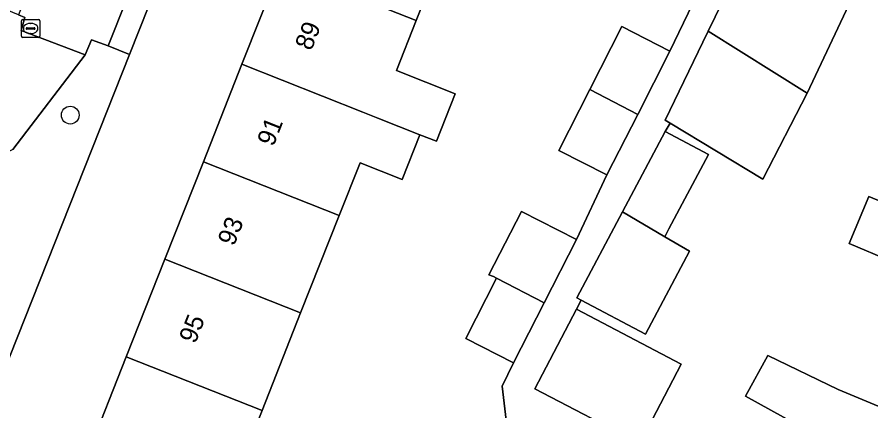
# Model space of a CAD drawing. Extents: x 160349 to 161355, y 381727 to 382854.
# Drawn here: x 160655.2 to 160702.07, y 382076.97 to 382098.58 of the extents above; entities that cross this region are included whole.
import ezdxf

# ---------------------------------------------------------------- set-up
doc = ezdxf.new("R2010")
doc.units = 0
for name, color, linetype in [('IMGEO_Boom', 7, 'Continuous'), ('IMGEO_Erf', 7, 'Continuous'), ('IMGEO_Pand', 7, 'Continuous'), ('IMGEO_Pand_nummerreeks', 7, 'Continuous'), ('IMGEO_Rioolput', 7, 'Continuous'), ('IMGEO_Voetpad_open', 7, 'Continuous'), ('IMGEO_Woonerf_open', 7, 'Continuous')]:
    doc.layers.add(name, color=color, linetype=linetype)

msp = doc.modelspace()

# ---------------------------------------------------------------- linework, layer by layer
at = {"layer": 'IMGEO_Boom'}
msp.add_circle((160658.122, 382093.2), 0.489, dxfattribs=at)
at = {"layer": 'IMGEO_Erf'}
msp.add_lwpolyline([(160669.66, 382101.331), (160671.777, 382106.678), (160673.894, 382112.022), (160676.01, 382117.368), (160678.127, 382122.713), (160680.243, 382128.058), (160682.36, 382133.403), (160684.476, 382138.748), (160686.593, 382144.093), (160688.754, 382149.551), (160683.199, 382151.736), (160672.819, 382125.35), (160661.371, 382096.521), (160642.897, 382049.998), (160648.453, 382047.774), (160650.611, 382053.225), (160652.728, 382058.571), (160654.845, 382063.916), (160656.961, 382069.26), (160659.078, 382074.606), (160661.194, 382079.95), (160663.311, 382085.296), (160665.428, 382090.642), (160667.544, 382095.987)], close=True, dxfattribs=at)
for points in [[(160704.153, 382106.281), (160701.477, 382100.582), (160698.578, 382094.409), (160698.573, 382094.398), (160696.131, 382089.694), (160691.048, 382092.76), (160690.773, 382092.304), (160693.15, 382091.042), (160690.98, 382086.953), (160690.754, 382086.527), (160692.107, 382085.735), (160689.691, 382081.183), (160686.167, 382083.054), (160685.905, 382082.561), (160691.661, 382079.533), (160689.391, 382075.184)], [(160679.231, 382103.728), (160677.114, 382098.382), (160676.031, 382095.647), (160679.253, 382094.371), (160678.22, 382091.762), (160677.313, 382092.121), (160676.343, 382089.67), (160674.027, 382090.586), (160672.881, 382087.692), (160670.765, 382082.347), (160668.648, 382077.001), (160666.532, 382071.656)], [(160682.125, 382075.845), (160681.832, 382078.34), (160682.447, 382079.604), (160679.827, 382080.941), (160681.518, 382084.253), (160681.347, 382084.342), (160681.106, 382084.438), (160682.884, 382087.921), (160685.906, 382086.379), (160687.584, 382089.917), (160684.947, 382091.26), (160686.648, 382094.6), (160688.406, 382098.053), (160691.043, 382096.71), (160692.783, 382100.37)], [(160703.134, 382085.209), (160700.882, 382086.149), (160701.962, 382088.736), (160704.214, 382087.796)], [(160699.198, 382075.578), (160695.196, 382077.779), (160696.423, 382080.009), (160700.271, 382078.147), (160705.011, 382076.169)]]:
    msp.add_lwpolyline(points, dxfattribs=at)
at = {"layer": 'IMGEO_Pand'}
for points in [[(160677.114, 382098.382), (160679.231, 382103.728), (160671.777, 382106.678), (160669.66, 382101.331)], [(160693.141, 382097.801), (160698.573, 382094.398), (160698.578, 382094.409), (160701.477, 382100.582), (160695.79, 382103.252)], [(160677.114, 382098.382), (160669.66, 382101.331), (160667.544, 382095.987), (160674.184, 382093.359), (160674.998, 382093.037), (160677.313, 382092.121), (160678.22, 382091.762), (160679.253, 382094.371), (160676.031, 382095.647)], [(160691.043, 382096.71), (160688.406, 382098.053), (160686.648, 382094.6), (160689.275, 382093.237)], [(160698.573, 382094.398), (160693.141, 382097.801), (160693.107, 382097.731), (160690.776, 382092.924), (160691.048, 382092.76), (160696.131, 382089.694)], [(160677.313, 382092.121), (160674.998, 382093.037), (160674.184, 382093.359), (160667.544, 382095.987), (160665.428, 382090.642), (160672.881, 382087.692), (160674.027, 382090.586), (160676.343, 382089.67)], [(160689.275, 382093.237), (160686.648, 382094.6), (160684.947, 382091.26), (160687.584, 382089.917)], [(160693.15, 382091.042), (160690.773, 382092.304), (160688.43, 382087.889), (160690.754, 382086.527), (160690.98, 382086.953)], [(160663.311, 382085.296), (160670.765, 382082.347), (160672.881, 382087.692), (160665.428, 382090.642)], [(160710.019, 382088.329), (160708.968, 382085.811), (160704.214, 382087.796), (160701.962, 382088.736), (160700.882, 382086.149), (160703.134, 382085.209), (160715.659, 382079.98), (160717.79, 382085.085)], [(160685.906, 382086.379), (160682.884, 382087.921), (160681.106, 382084.438), (160681.347, 382084.342), (160681.518, 382084.253), (160684.129, 382082.899)], [(160692.107, 382085.735), (160690.754, 382086.527), (160688.43, 382087.889), (160685.93, 382083.18), (160686.167, 382083.054), (160689.691, 382081.183)], [(160661.194, 382079.95), (160668.648, 382077.001), (160670.765, 382082.347), (160663.311, 382085.296)], [(160684.129, 382082.899), (160681.518, 382084.253), (160679.827, 382080.941), (160682.447, 382079.604)], [(160685.905, 382082.561), (160683.626, 382078.193), (160689.391, 382075.184), (160691.661, 382079.533)], [(160661.194, 382079.95), (160659.078, 382074.606), (160666.532, 382071.656), (160668.648, 382077.001)], [(160700.271, 382078.147), (160696.423, 382080.009), (160695.196, 382077.779), (160699.198, 382075.578), (160711.651, 382070.378), (160713.624, 382075.104), (160705.911, 382078.324), (160705.011, 382076.169)]]:
    msp.add_lwpolyline(points, close=True, dxfattribs=at)
at = {"layer": 'IMGEO_Rioolput'}
for p, q in [((160655.446, 382097.524), (160655.446, 382098.376)), ((160655.521, 382098.45), (160656.373, 382098.45)), ((160655.934, 382098.23), (160655.959, 382098.23)), ((160656.447, 382098.376), (160656.447, 382097.524)), ((160655.705, 382097.944), (160655.705, 382097.956)), ((160656.143, 382097.907), (160655.745, 382097.907)), ((160655.748, 382097.993), (160656.146, 382097.993)), ((160655.957, 382097.67), (160655.932, 382097.67)), ((160656.189, 382097.956), (160656.189, 382097.944)), ((160656.373, 382097.45), (160655.521, 382097.45))]:
    msp.add_line(p, q, dxfattribs=at)
for points in [[(160655.446, 382097.524), (160655.446, 382098.376)], [(160655.521, 382098.45), (160656.373, 382098.45)], [(160656.447, 382098.376), (160656.447, 382097.524)], [(160656.373, 382097.45), (160655.521, 382097.45)]]:
    msp.add_lwpolyline(points, dxfattribs=at)
for centre, radius, start, end in [((160655.523, 382098.374), 0.0765, 91.552, 178.448), ((160655.523, 382098.374), 0.0765, 91.552, 178.448), ((160656.371, 382098.374), 0.0765, 1.552, 88.448), ((160656.371, 382098.374), 0.0765, 1.552, 88.448), ((160655.745, 382097.953), 0.0403, 85.8775, 175.7526), ((160655.742, 382097.943), 0.0366, 178.938, 274.7102), ((160656.146, 382097.95), 0.043, 264.8664, 352.4533), ((160656.15, 382097.955), 0.0386, 1.7309, 96.639), ((160655.523, 382097.526), 0.0765, 181.552, 268.448), ((160655.523, 382097.526), 0.0765, 181.552, 268.448), ((160656.371, 382097.526), 0.0765, 271.552, 358.448), ((160656.371, 382097.526), 0.0765, 271.552, 358.448)]:
    msp.add_arc(centre, radius, start, end, dxfattribs=at)
for centre, major_axis, ratio, start_param, end_param in [((160655.933, 382097.95), (-0.387, 0.002), 0.722429, 4.712389, 7.853982), ((160655.958, 382097.95), (-0.39, 0.002), 0.717154, 1.570796, 4.712389)]:
    msp.add_ellipse(centre, major_axis=major_axis, ratio=ratio, start_param=start_param, end_param=end_param, dxfattribs=at)
at = {"layer": 'IMGEO_Voetpad_open'}
for points in [[(160674.662, 382139.353), (160671.062, 382130.085), (160669.801, 382126.839), (160668.154, 382122.601), (160667.897, 382121.939), (160668.937, 382121.552), (160667.248, 382117.228), (160664.699, 382110.704), (160665.519, 382110.365), (160660.198, 382097.004), (160661.371, 382096.521), (160672.819, 382125.35), (160683.199, 382151.736)], [(160704.977, 382067.37), (160701.97, 382068.631), (160696.328, 382071.375), (160689.391, 382075.184), (160683.626, 382078.193), (160685.905, 382082.561), (160686.167, 382083.054), (160685.93, 382083.18), (160688.43, 382087.889), (160690.773, 382092.304), (160691.048, 382092.76), (160690.776, 382092.924), (160693.107, 382097.731), (160693.141, 382097.801), (160695.79, 382103.252), (160698.655, 382109.15), (160701.506, 382115.018), (160701.766, 382114.909), (160706.387, 382123.75)], [(160703.159, 382121.024), (160701.44, 382117.39), (160699.598, 382113.899), (160697.818, 382110.526), (160696.952, 382108.872), (160696.016, 382107.084), (160694.346, 382103.616), (160692.783, 382100.37), (160691.043, 382096.71), (160689.275, 382093.237), (160687.584, 382089.917), (160685.906, 382086.379), (160684.129, 382082.899), (160682.447, 382079.604), (160681.832, 382078.34), (160682.125, 382075.845)], [(160654.96, 382091.32), (160658.94, 382096.501), (160655.419, 382097.832), (160655.627, 382098.562), (160655.285, 382098.702), (160651.466, 382100.264)], [(160661.371, 382096.521), (160660.198, 382097.004), (160659.288, 382097.322), (160658.94, 382096.501), (160654.96, 382091.32), (160654.517, 382091.09), (160654.042, 382089.9), (160653.879, 382089.553), (160653.718, 382089.205)], [(160629.825, 382022.664), (160634.111, 382021.11), (160632.646, 382023.106), (160641.875, 382046.842), (160641.985, 382047.125), (160642.897, 382049.998), (160661.371, 382096.521)]]:
    msp.add_lwpolyline(points, dxfattribs=at)
at = {"layer": 'IMGEO_Woonerf_open'}
msp.add_lwpolyline([(160665.519, 382110.365), (160664.699, 382110.704), (160664.643, 382110.561), (160660.563, 382112.113), (160655.285, 382098.702), (160655.627, 382098.562), (160655.419, 382097.832), (160658.94, 382096.501), (160659.288, 382097.322), (160660.198, 382097.004)], close=True, dxfattribs=at)

# ---------------------------------------------------------------- texts
at = {"layer": 'IMGEO_Pand_nummerreeks'}
for s, rotation, p in [('89', 68.3997, (160671.349, 382096.687)), ('91', 68.3997, (160669.27, 382091.435)), ('93', 68.3977, (160667.107, 382085.973)), ('95', 68.3977, (160664.985, 382080.617))]:
    msp.add_text(s, height=1, rotation=rotation, dxfattribs=at).set_placement(p)

doc.saveas('drawing.dxf')
